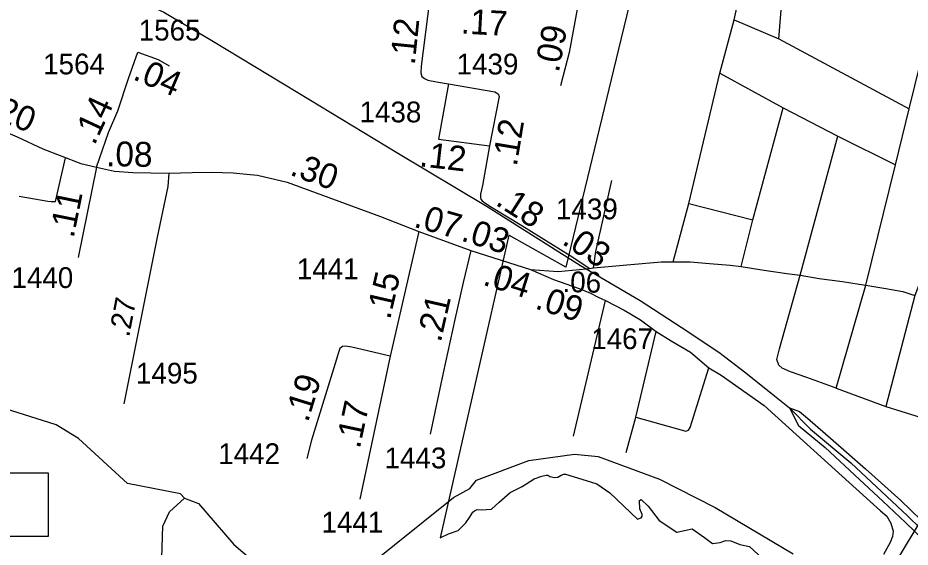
# Model space of a CAD drawing. Extents: x 2290615 to 2522933, y 819489 to 1012715.
# Drawn here: x 2385868 to 2391237, y 987517 to 990702 of the extents above; entities that cross this region are included whole.
import ezdxf

# ---------------------------------------------------------------- set-up
doc = ezdxf.new("R2010")
doc.units = 0
for name, color, linetype in [('Exist Boundary Political City Limit New', 7, 'Continuous'), ('Exist Boundary Political City Limit Old', 7, 'Continuous'), ('Exist Hydrographic Creek Single Shore', 7, 'Continuous'), ('Exist Hydrographic Misc Water Feature', 7, 'Continuous'), ('Exist Railroad Mainline', 7, 'Continuous'), ('Exist Railroad Siding', 7, 'Continuous'), ('Exist Road Non-System Type 51', 7, 'Continuous'), ('Exist Road Secondary Mileage Hundredths English Label', 7, 'Continuous'), ('Exist Road Secondary Mileage Tenths English Label', 7, 'Continuous'), ('Exist Road Secondary Structure Pipe Number Label', 7, 'Continuous'), ('Exist Road Secondary Structure Standard Bridge Number Label', 7, 'Continuous'), ('Exist Road Secondary Type 51 Attributed', 7, 'Continuous'), ('Exist Road Secondary Type 51 Number Label', 7, 'Continuous'), ('Map Preparation Boundary City Limit Buffer Line', 7, 'Continuous')]:
    doc.layers.add(name, color=color, linetype=linetype)

msp = doc.modelspace()

# ---------------------------------------------------------------- linework, layer by layer
at = {"layer": 'Exist Boundary Political City Limit New'}
for points in [[(2389834.7, 993793.2), (2389783.4, 992767.3), (2389732, 991645.7), (2389714.9, 991471.4), (2389495.8, 990572), (2389165.5, 989202.6), (2388821.5, 989394), (2388409.6, 987574.3), (2388459.7, 987598.2), (2388518.4, 987617.1), (2388564.5, 987663.1), (2388585.3, 987695.1), (2388606.7, 987727.6), (2388616.2, 987735.6), (2388632.5, 987744.6), (2388658.7, 987742.6), (2388717.4, 987746.8), (2388764.3, 987787)], [(2388764.3, 987787), (2388829.9, 987846.6), (2388901.9, 987881.4), (2388973.9, 987928.5), (2389021.1, 987943.4), (2389047.2, 987950.9), (2389056.9, 987950.2), (2389069, 987941.8), (2389096.8, 987936.3), (2389118, 987938.8), (2389136.8, 987950.9), (2389153.8, 987956.9), (2389162.7, 987955.8), (2389262, 987926), (2389351.4, 987898.7), (2389430.9, 987844.1), (2389595.6, 987684.7), (2389619, 987693.7), (2389624.4, 987702.7), (2389623.8, 987712.9), (2389610.6, 987747.1), (2389608.8, 987798.1), (2389619, 987803.5), (2389660.5, 987763.9), (2389727.2, 987678.1), (2389832.8, 987606.6), (2389926.1, 987626.9), (2390000.1, 987574.7), (2390047.2, 987539.7), (2390092.9, 987545.1), (2390127.5, 987557.2), (2390158.6, 987554.5), (2390213.2, 987532.9), (2390271, 987521.5), (2390510.4, 987298.6)]]:
    msp.add_lwpolyline(points, dxfattribs=at)
at = {"layer": 'Exist Boundary Political City Limit Old'}
for points in [[(2389834.7, 993793.2), (2389783.4, 992767.3), (2389732, 991645.7), (2389714.9, 991471.4), (2389495.8, 990572), (2389165.5, 989202.6), (2388821.5, 989394), (2388409.6, 987574.3), (2388459.7, 987598.2), (2388518.4, 987617.1), (2388564.5, 987663.1), (2388585.3, 987695.1), (2388606.7, 987727.6), (2388616.2, 987735.6), (2388632.5, 987744.6), (2388658.7, 987742.6), (2388717.4, 987746.8), (2388764.3, 987787)], [(2388764.3, 987787), (2388829.9, 987846.6), (2388901.9, 987881.4), (2388973.9, 987928.5), (2389021.1, 987943.4), (2389047.2, 987950.9), (2389056.9, 987950.2), (2389069, 987941.8), (2389096.8, 987936.3), (2389118, 987938.8), (2389136.8, 987950.9), (2389153.8, 987956.9), (2389162.7, 987955.8), (2389262, 987926), (2389351.4, 987898.7), (2389430.9, 987844.1), (2389595.6, 987684.7), (2389619, 987693.7), (2389624.4, 987702.7), (2389623.8, 987712.9), (2389610.6, 987747.1), (2389608.8, 987798.1), (2389619, 987803.5), (2389660.5, 987763.9), (2389727.2, 987678.1), (2389832.8, 987606.6), (2389926.1, 987626.9), (2390000.1, 987574.7), (2390047.2, 987539.7), (2390092.9, 987545.1), (2390127.5, 987557.2), (2390158.6, 987554.5), (2390213.2, 987532.9), (2390271, 987521.5), (2390510.4, 987298.6)]]:
    msp.add_lwpolyline(points, dxfattribs=at)
at = {"layer": 'Exist Hydrographic Creek Single Shore'}
for points in [[(2386871.5, 987812.4), (2386846.4, 987837.6), (2386528.4, 987900.1), (2386233.5, 988170.3), (2386099.4, 988253.3), (2385672.5, 988386.8), (2385403.5, 988602.3), (2385143.5, 988732.7), (2384865.9, 989038.6), (2384816.4, 989072.5), (2384769.4, 989084.2), (2384667.8, 989085.5), (2384602.6, 989105.1)], [(2387952.5, 987384.1), (2388488.5, 987816.6), (2388587.5, 987869.9), (2388628.5, 987920.8), (2388943.5, 988038.8), (2389217.5, 988076.4), (2389359.4, 988062.5), (2389728.4, 987926.7), (2390063.5, 987756.6), (2390533.5, 987477.2)], [(2386871.5, 987812.4), (2386955.5, 987779.8), (2387167.6, 987532.4), (2387369.5, 987360.1)]]:
    msp.add_lwpolyline(points, dxfattribs=at)
at = {"layer": 'Exist Hydrographic Misc Water Feature'}
msp.add_lwpolyline([(2384151.1, 984921), (2384765.6, 985142.1), (2385095.5, 985438), (2385266.5, 985701.2), (2385378.5, 986050.5), (2385456.4, 986493.5), (2385504.6, 986587.5), (2385693.4, 986815.2), (2385850.5, 986900.5), (2386174.5, 987002.4), (2386614.5, 987082.9), (2386728.5, 987261.6), (2386740.4, 987642.9), (2386781.4, 987729.9), (2386871.5, 987812.4)], dxfattribs=at)
at = {"layer": 'Exist Railroad Mainline'}
for points in [[(2385655.6, 991097.3), (2385912.5, 991030.6), (2386129.4, 990967.5), (2386340.2, 990902.3), (2386587.5, 990807.6), (2386746.3, 990735.7), (2387034.5, 990565.6), (2387552.7, 990252.5), (2388149.3, 989892.4), (2388691.6, 989565.7), (2389254.1, 989211.2), (2389612.9, 989002), (2389859.1, 988841.2), (2390085, 988690.2), (2390248.6, 988566.4), (2390420.5, 988426.8), (2390511.4, 988355.9)], [(2390511.4, 988355.9), (2390637, 988227.6), (2390879.7, 988024.8), (2391221.8, 987705.5), (2391455, 987476.5), (2391716.2, 987222.1), (2391876.5, 987056.2), (2392182.4, 986762.3), (2392433.6, 986517.7)]]:
    msp.add_lwpolyline(points, dxfattribs=at)
at = {"layer": 'Exist Railroad Siding'}
for points in [[(2390511.4, 988355.9), (2390571.6, 988332.8), (2390620.3, 988293.3), (2390773.9, 988159.6), (2390968.2, 987988), (2391180.8, 987798.8), (2391363, 987621.4), (2391561.4, 987438.1), (2391741.8, 987256.4), (2391954.7, 987039.2), (2392110.7, 986885.3), (2392274.7, 986727.5), (2392355.8, 986648.6), (2392410.5, 986593.4), (2392433.6, 986517.7)], [(2390511.4, 988355.9), (2390564.9, 988248.6), (2390726.6, 988116.8), (2390933.1, 987923.5), (2391072.7, 987793.4), (2391208.5, 987665.3), (2391319.9, 987558.8), (2391490.2, 987385.1), (2391672.4, 987211.5), (2391848.7, 987041.8), (2392079.5, 986815), (2392209.3, 986682.6), (2392274.1, 986619.6), (2392433.6, 986517.7)]]:
    msp.add_lwpolyline(points, dxfattribs=at)
at = {"layer": 'Exist Road Non-System Type 51'}
for p, q in [((2390447.5, 990576), (2390475.2, 990944.8)), ((2390447.5, 990576), (2390475.2, 990944.8)), ((2390178.7, 990689.7), (2390217.5, 990871.3)), ((2390178.7, 990689.7), (2390217.5, 990871.3)), ((2390092.1, 990369.4), (2390178.7, 990689.7)), ((2390092.1, 990369.4), (2390178.7, 990689.7)), ((2390178.7, 990689.7), (2390447.5, 990576)), ((2390178.7, 990689.7), (2390447.5, 990576)), ((2390447.5, 990576), (2391231.2, 990153.7)), ((2390447.5, 990576), (2391231.2, 990153.7)), ((2391231.2, 990153.7), (2391299.6, 990431.8)), ((2389904.6, 989584.6), (2390092.1, 990369.4)), ((2389904.6, 989584.6), (2390092.1, 990369.4)), ((2390092.1, 990369.4), (2390473.9, 990161.2)), ((2390092.1, 990369.4), (2390473.9, 990161.2)), ((2390291.1, 989486.5), (2390473.9, 990161.2)), ((2390291.1, 989486.5), (2390473.9, 990161.2)), ((2390473.9, 990161.2), (2390800.9, 989989.6)), ((2390473.9, 990161.2), (2390800.9, 989989.6)), ((2391148.7, 989817.9), (2391231.2, 990153.7)), ((2390800.9, 989989.6), (2391148.7, 989817.9)), ((2390800.9, 989989.6), (2391148.7, 989817.9)), ((2389810.5, 989234.6), (2389904.6, 989584.6)), ((2389810.5, 989234.6), (2389904.6, 989584.6)), ((2389904.6, 989584.6), (2390291.1, 989486.5)), ((2389904.6, 989584.6), (2390291.1, 989486.5)), ((2390221.2, 989204.7), (2390291.1, 989486.5)), ((2390221.2, 989204.7), (2390291.1, 989486.5)), ((2389211.9, 988184.8), (2389403.9, 989002.1)), ((2389211.9, 988184.8), (2389403.9, 989002.1)), ((2389586.2, 988299.6), (2389708.4, 988815.3)), ((2389586.2, 988299.6), (2389708.4, 988815.3)), ((2390791.1, 988473.5), (2391090.3, 988364.3)), ((2390791.1, 988473.5), (2391090.3, 988364.3)), ((2391090.3, 988364.3), (2391366.7, 988278)), ((2391090.3, 988364.3), (2391366.7, 988278)), ((2389529.1, 988087), (2389586.2, 988299.6)), ((2389529.1, 988087), (2389586.2, 988299.6))]:
    msp.add_line(p, q, dxfattribs=at)
for points in [[(2390791.1, 988473.5), (2390615, 988538.7), (2390516.4, 988572.2), (2390467.1, 988593.3), (2390446, 988612.7), (2390435.5, 988646.2), (2390451.3, 988709.6), (2390574.5, 989153.6), (2390800.9, 989989.6)], [(2385875.9, 989627.9), (2386049, 989598.8), (2386068.4, 989596), (2386094.8, 989597.4), (2386155.7, 989859.5)], [(2385875.9, 989627.9), (2386049, 989598.8), (2386068.4, 989596), (2386094.8, 989597.4), (2386155.7, 989859.5)], [(2390791.1, 988473.5), (2390970.6, 989093.7), (2391148.7, 989817.9)], [(2389330.9, 989197.3), (2389346.1, 989295.1), (2389442.6, 989722.6)], [(2391386, 989347.5), (2391264.6, 989032), (2391090.3, 988364.3)], [(2389403.9, 989002.1), (2389515.3, 988943.8), (2389615.1, 988884), (2389708.4, 988815.3)], [(2389403.9, 989002.1), (2389515.3, 988943.8), (2389615.1, 988884), (2389708.4, 988815.3)], [(2389708.4, 988815.3), (2389798.2, 988758.9), (2389914.4, 988690.2), (2390025.3, 988596.8)], [(2389708.4, 988815.3), (2389798.2, 988758.9), (2389914.4, 988690.2), (2390025.3, 988596.8)], [(2389586.2, 988299.6), (2389887.2, 988215.8), (2389903.2, 988221.8), (2389912.9, 988238), (2390025.3, 988596.8)], [(2389586.2, 988299.6), (2389887.2, 988215.8), (2389903.2, 988221.8), (2389912.9, 988238), (2390025.3, 988596.8)], [(2390025.3, 988596.8), (2390099.2, 988552.8), (2390359.2, 988369.8), (2390786.4, 987981.6), (2391059.5, 987735.2), (2391096, 987703.7), (2391120.5, 987662.1), (2391135.3, 987613), (2391130, 987581.3), (2391115.9, 987546), (2391077.2, 987473.8)], [(2390025.3, 988596.8), (2390099.2, 988552.8), (2390359.2, 988369.8), (2390786.4, 987981.6), (2391059.5, 987735.2), (2391096, 987703.7), (2391120.5, 987662.1), (2391135.3, 987613), (2391130, 987581.3), (2391115.9, 987546), (2391077.2, 987473.8)]]:
    msp.add_lwpolyline(points, dxfattribs=at)
at = {"layer": 'Exist Road Secondary Structure Pipe Number Label'}
msp.add_lwpolyline([(2384784.6, 987965.1), (2386050.8, 987965.1), (2386050.8, 987581.2), (2384784.6, 987581.2)], close=True, dxfattribs=at)
at = {"layer": 'Exist Road Secondary Structure Standard Bridge Number Label'}
msp.add_lwpolyline([(2391028.7, 987224.9), (2391552.1, 988091.7), (2392140.9, 987830)], dxfattribs=at)
at = {"layer": 'Exist Road Secondary Type 51 Attributed'}
for p, q in [((2386341.9, 989803.8), (2386231.9, 989259)), ((2388281.7, 989416), (2388109.2, 988665.4)), ((2388281.7, 989416), (2388593.3, 989301.4)), ((2388593.3, 989301.4), (2388952.4, 989186.9)), ((2388109.2, 988665.4), (2387925.1, 987805.7))]:
    msp.add_line(p, q, dxfattribs=at)
for points in [[(2388345.8, 990804.7), (2388294.9, 990411.8), (2388293.7, 990371.7), (2388298.3, 990348.8), (2388314.3, 990336.3), (2388336, 990326), (2388387.5, 990316.8), (2388458.4, 990304.2)], [(2389233.8, 990753.4), (2389185.5, 990493), (2389132.9, 990291.6)], [(2386341.9, 989803.8), (2386413.4, 990012), (2386469.8, 990142.9), (2386534, 990336.4), (2386590.8, 990494.5)], [(2386590.8, 990494.5), (2386712.7, 990451.5), (2386779.5, 990413.5)], [(2388458.4, 990304.2), (2388400, 989972.6)], [(2388458.4, 990304.2), (2388737.3, 990257.3), (2388749, 990251), (2388757.6, 990244.2), (2388764.5, 990227.6), (2388707, 989931.2)], [(2385375.1, 990195.5), (2385864.1, 989985.3), (2386019.5, 989912.8), (2386247.2, 989824.8), (2386341.9, 989803.8)], [(2388400, 989972.6), (2388707, 989931.2)], [(2388707, 989931.2), (2388663, 989693.2), (2388652.7, 989640.6), (2388651.6, 989620), (2388653.6, 989610.3), (2388661.9, 989600.6), (2388684.4, 989584.6), (2388717.6, 989563.4), (2388900.4, 989453.1), (2389190.9, 989271.6), (2389310.6, 989194.1)], [(2386341.9, 989803.8), (2386449.4, 989779), (2386560.3, 989770.7), (2386776.6, 989766.6)], [(2386776.6, 989766.6), (2386770.6, 989686.4), (2386707.1, 989382.2), (2386505.2, 988378.5)], [(2386776.6, 989766.6), (2386917.4, 989771.8), (2387035.4, 989773.6), (2387163.9, 989770.1), (2387244.9, 989761.3), (2387310, 989754.2), (2387487.8, 989713.7), (2388049.4, 989505.8), (2388281.7, 989416)], [(2388593.3, 989301.4), (2388547.5, 989109.4), (2388496.5, 988887.4), (2388427.8, 988565), (2388348.6, 988196.8)], [(2389287.1, 989191.9), (2389310.6, 989194.1)], [(2389310.6, 989194.1), (2389330.9, 989197.3), (2389511.2, 989213.5), (2389738.3, 989232.8), (2389810.5, 989234.6), (2389912.6, 989234.6), (2390028.8, 989224), (2390153.8, 989213.5), (2390221.2, 989204.7), (2390343.9, 989185.3), (2390495.3, 989164.1), (2390574.5, 989153.6), (2390689, 989134.2), (2390829.8, 989114.8), (2390930.1, 989099), (2390970.6, 989093.7), (2391090.3, 989072.5), (2391192.4, 989054.9), (2391264.6, 989032)], [(2388952.4, 989186.9), (2389118.7, 989176.5), (2389287.1, 989191.9)], [(2388952.4, 989186.9), (2389090.9, 989127), (2389245.9, 989073), (2389313.9, 989044.9), (2389359.9, 989021.4), (2389403.9, 989002.1)], [(2388109.2, 988665.4), (2387878.6, 988720.1), (2387838.1, 988727.1), (2387822.3, 988725.3), (2387806.4, 988713), (2387795, 988683.1), (2387785.3, 988647.8), (2387635, 988160.3), (2387607.1, 988050.2)]]:
    msp.add_lwpolyline(points, dxfattribs=at)
at = {"layer": 'Map Preparation Boundary City Limit Buffer Line'}
for points in [[(2389834.7, 993793.2), (2389783.4, 992767.3), (2389732, 991645.7), (2389714.9, 991471.4), (2389495.8, 990572), (2389165.5, 989202.6), (2388821.5, 989394), (2388409.6, 987574.3), (2388459.7, 987598.2), (2388518.4, 987617.1), (2388564.5, 987663.1), (2388585.3, 987695.1), (2388606.7, 987727.6), (2388616.2, 987735.6), (2388632.5, 987744.6), (2388658.7, 987742.6), (2388717.4, 987746.8), (2388764.3, 987787)], [(2388764.3, 987787), (2388829.9, 987846.6), (2388901.9, 987881.4), (2388973.9, 987928.5), (2389021.1, 987943.4), (2389047.2, 987950.9), (2389056.9, 987950.2), (2389069, 987941.8), (2389096.8, 987936.3), (2389118, 987938.8), (2389136.8, 987950.9), (2389153.8, 987956.9), (2389162.7, 987955.8), (2389262, 987926), (2389351.4, 987898.7), (2389430.9, 987844.1), (2389595.6, 987684.7), (2389619, 987693.7), (2389624.4, 987702.7), (2389623.8, 987712.9), (2389610.6, 987747.1), (2389608.8, 987798.1), (2389619, 987803.5), (2389660.5, 987763.9), (2389727.2, 987678.1), (2389832.8, 987606.6), (2389926.1, 987626.9), (2390000.1, 987574.7), (2390047.2, 987539.7), (2390092.9, 987545.1), (2390127.5, 987557.2), (2390158.6, 987554.5), (2390213.2, 987532.9), (2390271, 987521.5), (2390510.4, 987298.6)]]:
    msp.add_lwpolyline(points, dxfattribs=at)

# ---------------------------------------------------------------- texts
at = {"layer": 'Exist Road Secondary Mileage Hundredths English Label'}
for s, rotation, p in [('.30', 339.6857, (2387498.9, 989758.9)), ('.11', 78.5895, (2386203.8, 989372.4)), ('.15', 77.0545, (2388107.7, 988881.9)), ('.21', 77.0483, (2388412.4, 988744.8)), ('.19', 72.8711, (2387613.5, 988263.4)), ('.17', 77.9144, (2387925.3, 988105.3))]:
    msp.add_text(s, height=150, rotation=rotation, dxfattribs=at).set_placement(p)
at = {"layer": 'Exist Road Secondary Mileage Tenths English Label'}
for s, height, rotation, p in [('.17', 150, 356.7886, (2388531.3, 990607.6)), ('.12', 150, 84.1871, (2388256.1, 990414.2)), ('.09', 150, 79.2677, (2389122.5, 990368.2)), ('.04', 150, 336.8722, (2386554.2, 990334.3)), ('.20', 150, 337.5766, (2385678.8, 990114)), ('.14', 150, 65.0907, (2386329.5, 989930)), ('.12', 150, 80.5652, (2388869.4, 989804.1)), ('.08', 150, 358.9109, (2386398.4, 989809.6)), ('.12', 150, 353.3707, (2388280.1, 989809.3)), ('.18', 150, 327.3914, (2388735.6, 989580.4)), ('.07', 150, 344.2351, (2388244.5, 989445.4)), ('.03', 150, 342.4804, (2388529, 989363.1)), ('.03', 150, 326.4096, (2389135.9, 989345.2)), ('.04', 150, 342.4804, (2388659.9, 989097.1)), ('.06', 125, 358.8761, (2389144.3, 989052.1)), ('.09', 150, 342.4804, (2388973.9, 988954.3)), ('.27', 125, 79.1323, (2386537.5, 988776.8))]:
    msp.add_text(s, height=height, rotation=rotation, dxfattribs=at).set_placement(p)
at = {"layer": 'Exist Road Secondary Type 51 Number Label'}
for s, p in [('1565', (2386595.5, 990565.1)), ('1564', (2386020.4, 990361.6)), ('1439', (2388508.2, 990361)), ('1438', (2387924.1, 990072.9)), ('1439', (2389106.4, 989489.5)), ('1441', (2387546.5, 989129)), ('1440', (2385829.7, 989076.3)), ('1467', (2389317.9, 988708.6)), ('1495', (2386579.1, 988501.4)), ('1442', (2387073.8, 988016.9)), ('1443', (2388074.7, 987991.3)), ('1441', (2387695, 987604.8))]:
    msp.add_text(s, height=125, dxfattribs=at).set_placement(p)

doc.saveas('drawing.dxf')
